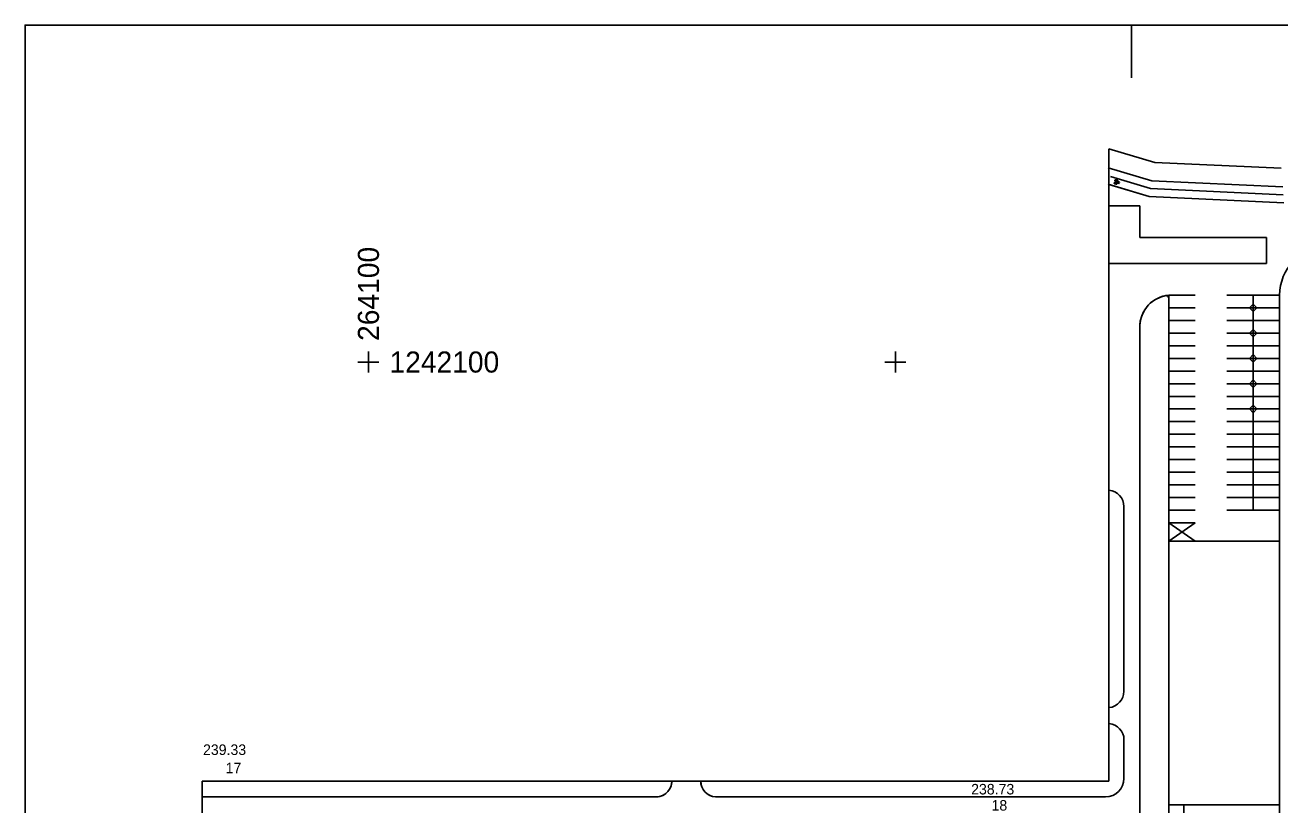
# Model space of a CAD drawing. Extents: x -264165 to -263575, y -1242333 to -1242036.
# Drawn here: x -264165.2 to -263927, y -1242184 to -1242036.1 of the extents above; entities that cross this region are included whole.
import ezdxf

# ---------------------------------------------------------------- set-up
doc = ezdxf.new("R2010")
doc.units = 0
for name, color, linetype in [('KFA_BODY_VYTYCOVAK', 7, 'Continuous'), ('KFA_HEKT_SIET_1-1000', 7, 'Continuous'), ('KFA_SITUACIA_DRS_VYTYCOVAK_SEDA', 7, 'Continuous'), ('RAM_NA_TLAC', 7, 'Continuous')]:
    doc.layers.add(name, color=color, linetype=linetype)

msp = doc.modelspace()

# ---------------------------------------------------------------- linework, layer by layer
at = {"layer": 'KFA_HEKT_SIET_1-1000'}
for p, q in [((-264100, -1242100), (-264100, -1242098)), ((-264000, -1242100), (-264000, -1242098)), ((-264100, -1242100), (-264102, -1242100)), ((-264100, -1242100), (-264098, -1242100)), ((-264100, -1242100), (-264100, -1242102)), ((-264000, -1242100), (-264002, -1242100)), ((-264000, -1242100), (-263998, -1242100)), ((-264000, -1242100), (-264000, -1242102))]:
    msp.add_line(p, q, dxfattribs=at)
at = {"layer": 'KFA_SITUACIA_DRS_VYTYCOVAK_SEDA'}
for p, q in [((-263950.75, -1242062.15), (-263959.47, -1242059.53)), ((-263959.47, -1242059.53), (-263959.47, -1242179.48)), ((-263950.75, -1242062.15), (-263959.47, -1242059.53)), ((-263951.34, -1242065.62), (-263959.61, -1242063.14)), ((-263926.77, -1242063.25), (-263950.75, -1242062.15)), ((-263926.77, -1242063.25), (-263950.75, -1242062.15)), ((-263951.59, -1242067.11), (-263959.18, -1242064.84)), ((-263958.34, -1242065.57), (-263958.35, -1242065.58)), ((-263958.35, -1242065.58), (-263958.35, -1242065.6)), ((-263958.35, -1242065.6), (-263958.34, -1242065.62)), ((-263958.33, -1242065.51), (-263958.34, -1242065.54)), ((-263958.34, -1242065.54), (-263958.34, -1242065.57)), ((-263958.34, -1242065.62), (-263958.34, -1242065.63)), ((-263958.34, -1242065.63), (-263958.33, -1242065.64)), ((-263958.32, -1242065.48), (-263958.33, -1242065.49)), ((-263958.33, -1242065.49), (-263958.33, -1242065.51)), ((-263958.33, -1242065.64), (-263958.32, -1242065.65)), ((-263958.31, -1242065.46), (-263958.32, -1242065.48)), ((-263958.32, -1242065.65), (-263958.31, -1242065.66)), ((-263958.3, -1242065.44), (-263958.31, -1242065.45)), ((-263958.31, -1242065.45), (-263958.31, -1242065.46)), ((-263958.31, -1242065.66), (-263958.29, -1242065.67)), ((-263958.28, -1242065.44), (-263958.3, -1242065.44)), ((-263958.29, -1242065.67), (-263958.27, -1242065.68)), ((-263958.27, -1242065.43), (-263958.28, -1242065.44)), ((-263958.25, -1242065.43), (-263958.27, -1242065.43)), ((-263958.24, -1242065.42), (-263958.25, -1242065.43)), ((-263958.22, -1242065.42), (-263958.24, -1242065.42)), ((-263958.19, -1242065.42), (-263958.22, -1242065.42)), ((-263958.17, -1242065.42), (-263958.19, -1242065.42)), ((-263958.14, -1242065.43), (-263958.17, -1242065.42)), ((-263958.11, -1242065.43), (-263958.14, -1242065.43)), ((-263958.07, -1242065.44), (-263958.11, -1242065.43)), ((-263958.04, -1242065.45), (-263958.07, -1242065.44)), ((-263958.07, -1242065.59), (-263957.46, -1242065.87)), ((-263958, -1242065.46), (-263958.04, -1242065.45)), ((-263957.97, -1242065.47), (-263958, -1242065.46)), ((-263957.94, -1242065.48), (-263957.97, -1242065.47)), ((-263957.91, -1242065.49), (-263957.94, -1242065.48)), ((-263957.89, -1242065.5), (-263957.91, -1242065.49)), ((-263957.87, -1242065.51), (-263957.89, -1242065.5)), ((-263957.85, -1242065.52), (-263957.87, -1242065.51)), ((-263957.84, -1242065.53), (-263957.85, -1242065.52)), ((-263957.82, -1242065.54), (-263957.84, -1242065.53)), ((-263957.81, -1242065.55), (-263957.82, -1242065.54)), ((-263957.82, -1242065.67), (-263957.81, -1242065.64)), ((-263957.82, -1242065.69), (-263957.82, -1242065.67)), ((-263957.81, -1242065.56), (-263957.81, -1242065.55)), ((-263957.8, -1242065.58), (-263957.81, -1242065.56)), ((-263957.81, -1242065.64), (-263957.8, -1242065.62)), ((-263957.8, -1242065.59), (-263957.8, -1242065.58)), ((-263957.8, -1242065.6), (-263957.8, -1242065.59)), ((-263957.8, -1242065.62), (-263957.8, -1242065.6)), ((-263926.5, -1242066.77), (-263951.34, -1242065.62)), ((-263951.84, -1242068.6), (-263959.61, -1242066.28)), ((-263959.47, -1242066.32), (-263959.47, -1242179.48)), ((-263951.84, -1242068.6), (-263959.47, -1242066.32)), ((-263958.46, -1242066.05), (-263958.47, -1242066.07)), ((-263958.47, -1242066.07), (-263958.47, -1242066.09)), ((-263958.47, -1242066.09), (-263958.47, -1242066.11)), ((-263958.47, -1242066.11), (-263958.47, -1242066.12)), ((-263958.47, -1242066.12), (-263958.46, -1242066.13)), ((-263958.45, -1242066), (-263958.46, -1242066.02)), ((-263958.46, -1242066.02), (-263958.46, -1242066.05)), ((-263958.46, -1242066.13), (-263958.45, -1242066.15)), ((-263958.44, -1242065.97), (-263958.45, -1242065.98)), ((-263958.45, -1242065.98), (-263958.45, -1242066)), ((-263958.45, -1242066.15), (-263958.44, -1242066.16)), ((-263958.43, -1242065.96), (-263958.44, -1242065.97)), ((-263958.44, -1242066.16), (-263958.43, -1242066.17)), ((-263958.42, -1242065.95), (-263958.43, -1242065.96)), ((-263958.43, -1242066.17), (-263958.42, -1242066.18)), ((-263958.41, -1242065.94), (-263958.42, -1242065.95)), ((-263958.42, -1242066.18), (-263958.4, -1242066.19)), ((-263958.4, -1242065.94), (-263958.41, -1242065.94)), ((-263958.38, -1242065.93), (-263958.4, -1242065.94)), ((-263958.4, -1242066.19), (-263958.37, -1242066.2)), ((-263958.36, -1242065.93), (-263958.38, -1242065.93)), ((-263958.37, -1242066.2), (-263958.35, -1242066.2)), ((-263958.34, -1242065.93), (-263958.36, -1242065.93)), ((-263958.35, -1242066.2), (-263958.32, -1242066.21)), ((-263958.32, -1242065.93), (-263958.34, -1242065.93)), ((-263958.29, -1242065.93), (-263958.32, -1242065.93)), ((-263958.32, -1242066.21), (-263958.23, -1242066.23)), ((-263958.26, -1242065.93), (-263958.29, -1242065.93)), ((-263958.27, -1242065.68), (-263958.25, -1242065.69)), ((-263958.23, -1242065.94), (-263958.26, -1242065.93)), ((-263958.25, -1242065.69), (-263958.22, -1242065.7)), ((-263958.2, -1242065.94), (-263958.23, -1242065.94)), ((-263958.23, -1242066.23), (-263958.15, -1242066.26)), ((-263958.22, -1242065.7), (-263958.19, -1242065.71)), ((-263958.16, -1242065.95), (-263958.2, -1242065.94)), ((-263958.19, -1242065.71), (-263958.11, -1242065.73)), ((-263958.14, -1242065.88), (-263958.19, -1242066.09)), ((-263957.69, -1242066.09), (-263958.19, -1242066.09)), ((-263958.13, -1242065.96), (-263958.16, -1242065.95)), ((-263958.15, -1242066.26), (-263958.12, -1242066.26)), ((-263958.14, -1242065.88), (-263957.69, -1242065.76)), ((-263958.14, -1242065.88), (-263957.69, -1242066.09)), ((-263958.09, -1242065.97), (-263958.13, -1242065.96)), ((-263958.12, -1242066.26), (-263958.09, -1242066.27)), ((-263958.11, -1242065.73), (-263958.02, -1242065.75)), ((-263958.06, -1242065.98), (-263958.09, -1242065.97)), ((-263958.09, -1242066.27), (-263958.06, -1242066.27)), ((-263958.04, -1242065.99), (-263958.06, -1242065.98)), ((-263958.06, -1242066.27), (-263958.04, -1242066.27)), ((-263958.01, -1242066), (-263958.04, -1242065.99)), ((-263958.04, -1242066.27), (-263958.02, -1242066.27)), ((-263958.02, -1242065.75), (-263957.99, -1242065.76)), ((-263958.02, -1242066.27), (-263958.01, -1242066.26)), ((-263957.99, -1242066.01), (-263958.01, -1242066)), ((-263958.01, -1242066.26), (-263957.99, -1242066.26)), ((-263957.99, -1242065.76), (-263957.96, -1242065.76)), ((-263957.98, -1242066.02), (-263957.99, -1242066.01)), ((-263957.99, -1242066.26), (-263957.98, -1242066.25)), ((-263957.96, -1242066.03), (-263957.98, -1242066.02)), ((-263957.98, -1242066.25), (-263957.97, -1242066.24)), ((-263957.97, -1242066.24), (-263957.96, -1242066.23)), ((-263957.96, -1242065.76), (-263957.94, -1242065.76)), ((-263957.95, -1242066.05), (-263957.96, -1242066.03)), ((-263957.96, -1242066.23), (-263957.95, -1242066.22)), ((-263957.94, -1242066.06), (-263957.95, -1242066.05)), ((-263957.95, -1242066.2), (-263957.94, -1242066.18)), ((-263957.95, -1242066.22), (-263957.95, -1242066.2)), ((-263957.94, -1242065.76), (-263957.92, -1242065.76)), ((-263957.93, -1242066.07), (-263957.94, -1242066.06)), ((-263957.94, -1242066.18), (-263957.93, -1242066.15)), ((-263957.93, -1242066.08), (-263957.93, -1242066.07)), ((-263957.93, -1242066.1), (-263957.93, -1242066.08)), ((-263957.93, -1242066.11), (-263957.93, -1242066.1)), ((-263957.93, -1242066.13), (-263957.93, -1242066.11)), ((-263957.93, -1242066.15), (-263957.93, -1242066.13)), ((-263957.92, -1242065.76), (-263957.9, -1242065.76)), ((-263957.9, -1242065.76), (-263957.88, -1242065.76)), ((-263957.88, -1242065.76), (-263957.87, -1242065.76)), ((-263957.87, -1242065.76), (-263957.86, -1242065.75)), ((-263957.86, -1242065.75), (-263957.85, -1242065.74)), ((-263957.85, -1242065.74), (-263957.84, -1242065.73)), ((-263957.84, -1242065.73), (-263957.83, -1242065.71)), ((-263957.83, -1242065.71), (-263957.82, -1242065.69)), ((-263957.69, -1242065.77), (-263957.62, -1242065.8)), ((-263957.62, -1242065.79), (-263957.69, -1242066.09)), ((-263957.69, -1242066.09), (-263957.57, -1242066.14)), ((-263957.56, -1242066.09), (-263957.58, -1242066.19)), ((-263957.46, -1242065.87), (-263957.48, -1242065.93)), ((-263926.39, -1242068.28), (-263951.59, -1242067.11)), ((-263953.62, -1242070.38), (-263959.47, -1242070.38)), ((-263959.47, -1242070.38), (-263959.47, -1242081.31)), ((-263959.47, -1242071.38), (-263959.47, -1242070.38)), ((-263959.47, -1242070.38), (-263953.62, -1242070.38)), ((-263953.62, -1242076.38), (-263953.62, -1242070.38)), ((-263953.62, -1242070.38), (-263953.62, -1242076.38)), ((-263926.27, -1242069.78), (-263951.84, -1242068.6)), ((-263926.27, -1242069.78), (-263951.84, -1242068.6)), ((-263959.47, -1242076.38), (-263959.47, -1242071.38)), ((-263959.47, -1242081.31), (-263959.47, -1242076.38)), ((-263953.62, -1242076.38), (-263929.58, -1242076.38)), ((-263953.62, -1242076.38), (-263929.58, -1242076.38)), ((-263929.58, -1242076.38), (-263929.58, -1242081.31)), ((-263929.58, -1242076.38), (-263929.58, -1242081.31)), ((-263929.58, -1242081.31), (-263959.47, -1242081.31)), ((-263953.62, -1242081.31), (-263959.47, -1242081.31)), ((-263929.58, -1242081.31), (-263953.62, -1242081.31)), ((-263948.09, -1242087.31), (-263948.59, -1242087.4)), ((-263948.09, -1242087.31), (-263948.09, -1242241.46)), ((-263948.09, -1242087.31), (-263943.09, -1242087.31)), ((-263948.09, -1242087.9), (-263948.09, -1242241.46)), ((-263937.09, -1242087.31), (-263932.09, -1242087.31)), ((-263932.8, -1242089.71), (-263932.09, -1242089)), ((-263932.8, -1242089.71), (-263932.09, -1242089)), ((-263932.09, -1242128.11), (-263932.09, -1242087.31)), ((-263927.09, -1242087.31), (-263932.09, -1242087.31)), ((-263932.09, -1242089), (-263931.39, -1242089.71)), ((-263932.09, -1242089), (-263931.39, -1242089.71)), ((-263927.09, -1242254.98), (-263927.09, -1242087.31)), ((-263948.09, -1242089.71), (-263943.09, -1242089.71)), ((-263937.09, -1242089.71), (-263932.09, -1242089.71)), ((-263932.09, -1242090.41), (-263932.8, -1242089.71)), ((-263932.09, -1242090.41), (-263932.8, -1242089.71)), ((-263931.39, -1242089.71), (-263932.09, -1242090.41)), ((-263927.09, -1242089.71), (-263932.09, -1242089.71)), ((-263931.39, -1242089.71), (-263932.09, -1242090.41)), ((-263953.62, -1242241.46), (-263953.62, -1242093.31)), ((-263953.62, -1242244.46), (-263953.62, -1242093.31)), ((-263948.09, -1242092.11), (-263943.09, -1242092.11)), ((-263937.09, -1242092.11), (-263932.09, -1242092.11)), ((-263932.8, -1242094.51), (-263932.09, -1242093.8)), ((-263932.8, -1242094.51), (-263932.09, -1242093.8)), ((-263927.09, -1242092.11), (-263932.09, -1242092.11)), ((-263932.09, -1242093.8), (-263931.39, -1242094.51)), ((-263932.09, -1242093.8), (-263931.39, -1242094.51)), ((-263948.09, -1242094.51), (-263943.09, -1242094.51)), ((-263937.09, -1242094.51), (-263932.09, -1242094.51)), ((-263932.09, -1242095.21), (-263932.8, -1242094.51)), ((-263932.09, -1242095.21), (-263932.8, -1242094.51)), ((-263931.39, -1242094.51), (-263932.09, -1242095.21)), ((-263927.09, -1242094.51), (-263932.09, -1242094.51)), ((-263931.39, -1242094.51), (-263932.09, -1242095.21)), ((-263948.09, -1242096.91), (-263943.09, -1242096.91)), ((-263937.09, -1242096.91), (-263932.09, -1242096.91)), ((-263932.8, -1242099.31), (-263932.09, -1242098.6)), ((-263932.8, -1242099.31), (-263932.09, -1242098.6)), ((-263927.09, -1242096.91), (-263932.09, -1242096.91)), ((-263932.09, -1242098.6), (-263931.39, -1242099.31)), ((-263932.09, -1242098.6), (-263931.39, -1242099.31)), ((-263948.09, -1242099.31), (-263943.09, -1242099.31)), ((-263937.09, -1242099.31), (-263932.09, -1242099.31)), ((-263932.09, -1242100.01), (-263932.8, -1242099.31)), ((-263932.09, -1242100.01), (-263932.8, -1242099.31)), ((-263931.39, -1242099.31), (-263932.09, -1242100.01)), ((-263927.09, -1242099.31), (-263932.09, -1242099.31)), ((-263931.39, -1242099.31), (-263932.09, -1242100.01)), ((-263948.09, -1242101.71), (-263943.09, -1242101.71)), ((-263937.09, -1242101.71), (-263932.09, -1242101.71)), ((-263932.8, -1242104.11), (-263932.09, -1242103.4)), ((-263932.8, -1242104.11), (-263932.09, -1242103.4)), ((-263927.09, -1242101.71), (-263932.09, -1242101.71)), ((-263932.09, -1242103.4), (-263931.39, -1242104.11)), ((-263932.09, -1242103.4), (-263931.39, -1242104.11)), ((-263959.47, -1242106.15), (-263959.47, -1242179.48)), ((-263948.09, -1242104.11), (-263943.09, -1242104.11)), ((-263937.09, -1242104.11), (-263932.09, -1242104.11)), ((-263932.09, -1242104.81), (-263932.8, -1242104.11)), ((-263932.09, -1242104.81), (-263932.8, -1242104.11)), ((-263931.39, -1242104.11), (-263932.09, -1242104.81)), ((-263927.09, -1242104.11), (-263932.09, -1242104.11)), ((-263931.39, -1242104.11), (-263932.09, -1242104.81)), ((-263948.09, -1242106.51), (-263943.09, -1242106.51)), ((-263937.09, -1242106.51), (-263932.09, -1242106.51)), ((-263932.8, -1242108.91), (-263932.09, -1242108.2)), ((-263927.09, -1242106.51), (-263932.09, -1242106.51)), ((-263932.09, -1242108.2), (-263931.39, -1242108.91)), ((-263948.09, -1242108.91), (-263943.09, -1242108.91)), ((-263937.09, -1242108.91), (-263932.09, -1242108.91)), ((-263932.09, -1242109.61), (-263932.8, -1242108.91)), ((-263927.09, -1242108.91), (-263932.09, -1242108.91)), ((-263931.39, -1242108.91), (-263932.09, -1242109.61)), ((-263948.09, -1242111.31), (-263943.09, -1242111.31)), ((-263937.09, -1242111.31), (-263932.09, -1242111.31)), ((-263927.09, -1242111.31), (-263932.09, -1242111.31)), ((-263948.09, -1242113.71), (-263943.09, -1242113.71)), ((-263937.09, -1242113.71), (-263932.09, -1242113.71)), ((-263927.09, -1242113.71), (-263932.09, -1242113.71)), ((-263948.09, -1242116.11), (-263943.09, -1242116.11)), ((-263937.09, -1242116.11), (-263932.09, -1242116.11)), ((-263927.09, -1242116.11), (-263932.09, -1242116.11)), ((-263948.09, -1242118.51), (-263943.09, -1242118.51)), ((-263937.09, -1242118.51), (-263932.09, -1242118.51)), ((-263927.09, -1242118.51), (-263932.09, -1242118.51)), ((-263948.09, -1242120.91), (-263943.09, -1242120.91)), ((-263937.09, -1242120.91), (-263932.09, -1242120.91)), ((-263927.09, -1242120.91), (-263932.09, -1242120.91)), ((-263959.47, -1242124.32), (-263959.47, -1242179.48)), ((-263948.09, -1242123.31), (-263943.09, -1242123.31)), ((-263937.09, -1242123.31), (-263932.09, -1242123.31)), ((-263927.09, -1242123.31), (-263932.09, -1242123.31)), ((-263956.62, -1242127.42), (-263956.62, -1242162.45)), ((-263956.62, -1242127.42), (-263956.62, -1242162.45)), ((-263956.62, -1242127.42), (-263956.62, -1242162.45)), ((-263948.09, -1242125.71), (-263943.09, -1242125.71)), ((-263937.09, -1242125.71), (-263932.09, -1242125.71)), ((-263927.09, -1242125.71), (-263932.09, -1242125.71)), ((-263948.09, -1242128.11), (-263943.09, -1242128.11)), ((-263937.09, -1242128.11), (-263931.59, -1242128.11)), ((-263927.09, -1242128.11), (-263931.59, -1242128.11)), ((-263948.09, -1242130.51), (-263943.09, -1242130.51)), ((-263943.09, -1242130.51), (-263948.09, -1242134.01)), ((-263943.09, -1242134.01), (-263948.09, -1242130.51)), ((-263948.09, -1242134.01), (-263942.59, -1242134.01)), ((-263927.09, -1242134.01), (-263948.09, -1242134.01)), ((-263948.09, -1242134.01), (-263948.09, -1242184.01)), ((-263927.09, -1242184.01), (-263927.09, -1242134.01)), ((-263956.62, -1242178.98), (-263956.62, -1242171.65)), ((-263956.62, -1242178.98), (-263956.62, -1242171.65)), ((-264077.23, -1242179.48), (-264131.57, -1242179.48)), ((-264131.57, -1242179.48), (-264131.57, -1242191.48)), ((-264131.57, -1242182.48), (-264131.57, -1242179.48)), ((-264131.57, -1242179.48), (-263959.47, -1242179.48)), ((-263959.47, -1242179.48), (-264131.57, -1242179.48)), ((-264131.57, -1242193.48), (-264131.57, -1242179.48)), ((-264077.23, -1242179.48), (-264131.57, -1242179.48)), ((-264131.57, -1242179.48), (-264131.57, -1242191.48)), ((-264131.57, -1242179.48), (-263959.47, -1242179.48)), ((-263959.47, -1242179.48), (-264077.23, -1242179.48)), ((-263959.47, -1242179.48), (-264077.23, -1242179.48)), ((-264042.46, -1242180.03), (-264042.42, -1242179.48)), ((-264036.89, -1242180.04), (-264036.95, -1242179.48)), ((-264045.2, -1242182.48), (-264044.54, -1242182.36)), ((-264044.54, -1242182.36), (-264044.03, -1242182.15)), ((-264044.03, -1242182.15), (-264043.57, -1242181.86)), ((-264043.57, -1242181.86), (-264043.17, -1242181.48)), ((-264043.17, -1242181.48), (-264042.85, -1242181.04)), ((-264042.85, -1242181.04), (-264042.61, -1242180.55)), ((-264042.61, -1242180.55), (-264042.46, -1242180.03)), ((-264036.74, -1242180.58), (-264036.89, -1242180.04)), ((-264036.49, -1242181.09), (-264036.74, -1242180.58)), ((-264036.14, -1242181.53), (-264036.49, -1242181.09)), ((-264035.72, -1242181.91), (-264036.14, -1242181.53)), ((-264035.24, -1242182.2), (-264035.72, -1242181.91)), ((-264034.71, -1242182.39), (-264035.24, -1242182.2)), ((-264045.2, -1242182.48), (-264131.57, -1242182.48)), ((-264045.2, -1242182.48), (-264131.57, -1242182.48)), ((-264045.2, -1242182.48), (-264131.57, -1242182.48)), ((-264034.16, -1242182.48), (-264034.71, -1242182.39)), ((-263960.12, -1242182.48), (-264034.16, -1242182.48)), ((-263960.12, -1242182.48), (-264034.16, -1242182.48)), ((-263960.12, -1242182.48), (-264034.16, -1242182.48)), ((-263948.09, -1242184.01), (-263927.09, -1242184.01)), ((-263945.26, -1242189.38), (-263945.26, -1242184.01))]:
    msp.add_line(p, q, dxfattribs=at)
for centre, radius, start, end in [((-263918.09, -1242087.31), 9, 90, 180), ((-263947.63, -1242093.3), 5.98, 94.3969, 180.066), ((-263947.63, -1242093.3), 5.98, 100.0694, 180.066), ((-263948.59, -1242087.9), 0.5, 0, 100.0694), ((-263959.74, -1242127.43), 3.12, 0.1518, 85.0363), ((-263959.74, -1242127.43), 3.12, 0.1518, 85.0363), ((-263959.74, -1242127.43), 3.12, 0.1518, 85.0363), ((-263959.74, -1242162.44), 3.12, 274.9637, 359.8482), ((-263959.74, -1242162.44), 3.12, 274.9637, 359.8482), ((-263959.74, -1242162.44), 3.12, 274.9637, 359.8482), ((-263959.67, -1242171.63), 3.05, 359.6441, 86.2155), ((-263959.67, -1242171.63), 3.05, 359.6441, 86.2155), ((-264045.41, -1242179.5), 2.99, 266.0314, 0.25), ((-264033.95, -1242179.5), 2.99, 179.75, 266.0314), ((-263960.12, -1242178.98), 3.5, 270, 0), ((-263960.12, -1242178.98), 3.5, 270, 0), ((-263960.12, -1242178.98), 3.5, 270, 0)]:
    msp.add_arc(centre, radius, start, end, dxfattribs=at)
at = {"layer": 'RAM_NA_TLAC'}
msp.add_line((-263955.16, -1242046.09), (-263955.16, -1242036.09), dxfattribs=at)
msp.add_lwpolyline([(-264165.16, -1242333.09), (-264165.16, -1242036.09), (-263955.16, -1242036.09), (-263575.16, -1242036.09), (-263575.16, -1242333.09), (-263955.16, -1242333.09)], close=True, dxfattribs=at)

# ---------------------------------------------------------------- texts
at = {"layer": 'KFA_BODY_VYTYCOVAK'}
for s, p in [('239.33', (-264131.39, -1242174.54)), ('17', (-264127.1, -1242178.01)), ('238.73', (-263985.62, -1242182.03)), ('18', (-263981.75, -1242185.09))]:
    msp.add_text(s, height=2, dxfattribs=at).set_placement(p)
at = {"layer": 'KFA_HEKT_SIET_1-1000'}
msp.add_text('264100', height=4, rotation=90, dxfattribs=at).set_placement((-264098, -1242096))
msp.add_text('1242100', height=4, dxfattribs=at).set_placement((-264096, -1242102))

doc.saveas('drawing.dxf')
